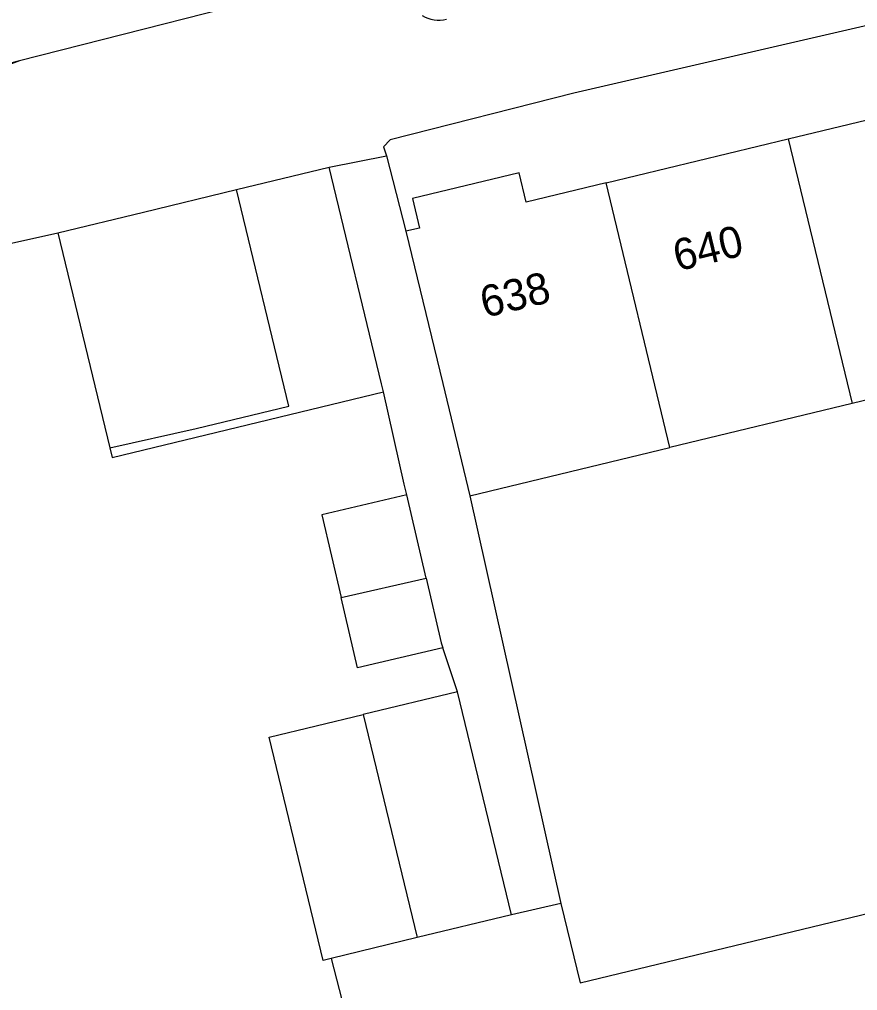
# Model space of a CAD drawing. Extents: x 157793 to 159380, y 380882 to 382313.
# Drawn here: x 158775.1 to 158801.85, y 381293.1 to 381324.1 of the extents above; entities that cross this region are included whole.
import ezdxf

# ---------------------------------------------------------------- set-up
doc = ezdxf.new("R2010")
doc.units = 0
for name, color, linetype in [('IMGEO_Muur', 7, 'Continuous'), ('IMGEO_Pand', 7, 'Continuous'), ('IMGEO_Pand_nummerreeks', 7, 'Continuous'), ('IMGEO_Rijbaan_lokaal_gesloten', 7, 'Continuous'), ('IMGEO_Rijbaan_lokaal_open', 7, 'Continuous'), ('IMGEO_Voetpad_open', 7, 'Continuous')]:
    doc.layers.add(name, color=color, linetype=linetype)

msp = doc.modelspace()

# ---------------------------------------------------------------- linework, layer by layer
at = {"layer": 'IMGEO_Muur'}
msp.add_lwpolyline([(158762.646, 381314.243), (158776.325, 381317.292)], dxfattribs=at)
at = {"layer": 'IMGEO_Pand'}
for points in [[(158799.634, 381320.286), (158805.735, 381321.76)], [(158793.819, 381318.881), (158799.634, 381320.286)], [(158799.634, 381320.286), (158801.674, 381311.843)], [(158782.022, 381318.668), (158784.986, 381319.384)], [(158786.72, 381312.211), (158786.657, 381312.472), (158784.986, 381319.384)], [(158793.819, 381318.881), (158791.271, 381318.265), (158791.043, 381319.208), (158787.641, 381318.386), (158787.869, 381317.443), (158787.432, 381317.337)], [(158776.325, 381317.292), (158779.062, 381317.953), (158782.022, 381318.668)], [(158777.985, 381310.422), (158780.735, 381311.04), (158783.695, 381311.755), (158782.022, 381318.668)], [(158795.86, 381310.437), (158793.819, 381318.881)], [(158776.325, 381317.292), (158777.985, 381310.422)], [(158787.432, 381317.337), (158788.606, 381312.477), (158789.472, 381308.894)], [(158807.775, 381313.317), (158808.527, 381310.208), (158806.071, 381309.614), (158805.319, 381312.724), (158801.674, 381311.843)], [(158777.985, 381310.422), (158778.058, 381310.118), (158786.72, 381312.211)], [(158801.674, 381311.843), (158795.86, 381310.437)], [(158789.472, 381308.894), (158795.86, 381310.437)], [(158787.457, 381308.922), (158784.747, 381308.289), (158785.364, 381305.646)], [(158788.076, 381306.266), (158787.457, 381308.922)], [(158785.364, 381305.646), (158788.076, 381306.266)], [(158788.076, 381306.266), (158788.558, 381304.201), (158788.612, 381304.039)], [(158788.612, 381304.039), (158785.887, 381303.404), (158785.364, 381305.646)], [(158789.076, 381302.641), (158786.07, 381301.915)], [(158790.798, 381295.518), (158789.076, 381302.641)], [(158785.047, 381294.128), (158784.788, 381294.066), (158783.067, 381301.189), (158786.07, 381301.915)], [(158786.07, 381301.915), (158787.795, 381294.792)], [(158790.798, 381295.518), (158787.795, 381294.792)], [(158787.795, 381294.792), (158785.047, 381294.128)]]:
    msp.add_lwpolyline(points, dxfattribs=at)
at = {"layer": 'IMGEO_Rijbaan_lokaal_gesloten'}
for points in [[(158785.167, 381325.349), (158784.979, 381325.299), (158775.099, 381322.78)], [(158775.099, 381322.78), (158754.389, 381317.404)]]:
    msp.add_lwpolyline(points, dxfattribs=at)
at = {"layer": 'IMGEO_Rijbaan_lokaal_open'}
for points in [[(158792.376, 381295.882), (158792.989, 381293.347), (158817.628, 381299.302), (158818.196, 381296.951), (158830.799, 381299.997)], [(158792.376, 381295.882), (158790.798, 381295.518)], [(158785.047, 381294.128), (158785.719, 381291.531), (158759.787, 381285.61)]]:
    msp.add_lwpolyline(points, dxfattribs=at)
at = {"layer": 'IMGEO_Voetpad_open'}
for points in [[(158826.172, 381328.554), (158812.22, 381325.346), (158812.013, 381326.196), (158792.792, 381321.742), (158786.929, 381320.261), (158786.713, 381320.031), (158786.81, 381319.749)], [(158784.986, 381319.384), (158786.81, 381319.749)], [(158786.81, 381319.749), (158787.432, 381317.337)], [(158754.804, 381306.261), (158753.371, 381312.226), (158755.24, 381312.683), (158762.646, 381314.243), (158776.325, 381317.292)], [(158787.457, 381308.922), (158787.376, 381309.268), (158786.72, 381312.211)], [(158789.472, 381308.894), (158792.376, 381295.882)], [(158789.076, 381302.641), (158788.612, 381304.039)]]:
    msp.add_lwpolyline(points, dxfattribs=at)
for centre, radius, start, end in [((158788.47, 381325.092), 1.012, 239.319, 284.8143), ((158775.674, 381320.921), 1.946, 107.203, 149.153)]:
    msp.add_arc(centre, radius, start, end, dxfattribs=at)

# ---------------------------------------------------------------- texts
at = {"layer": 'IMGEO_Pand_nummerreeks'}
for s, rotation, p in [('640', 13.5872, (158796.1, 381316.057)), ('638', 13.5848, (158789.944, 381314.57))]:
    msp.add_text(s, height=1, rotation=rotation, dxfattribs=at).set_placement(p)

doc.saveas('drawing.dxf')
